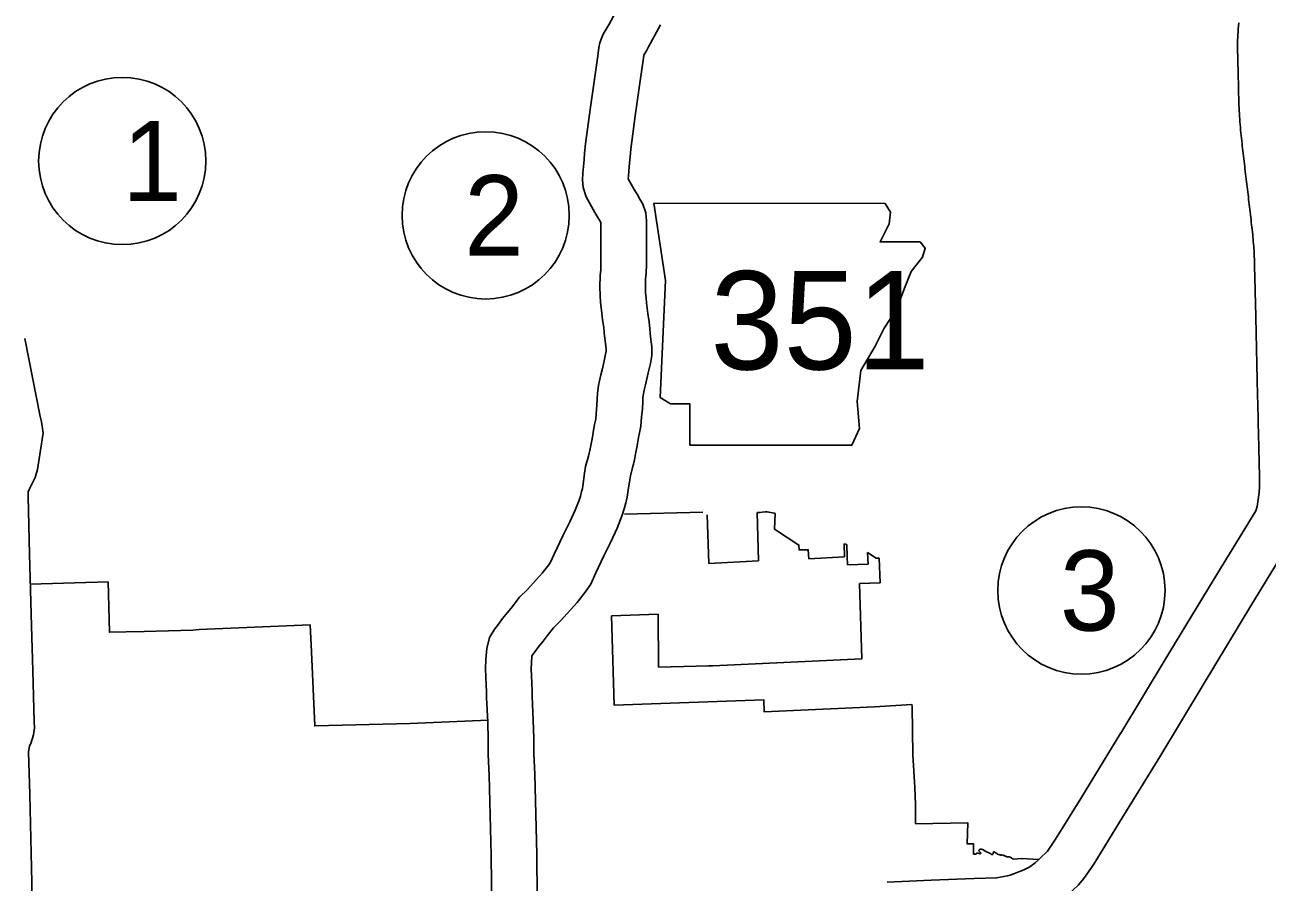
# Model space of a CAD drawing. Extents: x 1671357 to 13005564, y 567358 to 14261451.
# Drawn here: x 12758288.351 to 12758289.241, y 14259954.141 to 14259954.755 of the extents above; entities that cross this region are included whole.
import ezdxf

# ---------------------------------------------------------------- set-up
doc = ezdxf.new("R2010")
doc.units = 0
for name, color, linetype in [('10', 7, 'Continuous'), ('15', 7, 'Continuous'), ('21', 7, 'Continuous'), ('40', 7, 'Continuous'), ('6', 7, 'Continuous')]:
    doc.layers.add(name, color=color, linetype=linetype)

msp = doc.modelspace()

# ---------------------------------------------------------------- linework, layer by layer
at = {"layer": '10'}
for points in [[(12758288.7775, 14259954.76969), (12758288.7693, 14259954.75449), (12758288.7683, 14259954.75271), (12758288.76535, 14259954.74802), (12758288.76398, 14259954.74444), (12758288.76306, 14259954.74171), (12758288.76235, 14259954.73843), (12758288.76145, 14259954.73229), (12758288.7586, 14259954.71236), (12758288.75593, 14259954.69397), (12758288.7526, 14259954.6693), (12758288.75201, 14259954.66267), (12758288.75172, 14259954.6581), (12758288.75124, 14259954.65321), (12758288.75077, 14259954.64835), (12758288.75063, 14259954.64354), (12758288.75105, 14259954.63821), (12758288.75313, 14259954.63138), (12758288.75936, 14259954.62033), (12758288.7615, 14259954.61671), (12758288.76342, 14259954.61343), (12758288.76379, 14259954.6128), (12758288.7637, 14259954.60079), (12758288.76379, 14259954.59004), (12758288.76375, 14259954.58362), (12758288.76365, 14259954.57915), (12758288.76313, 14259954.57511), (12758288.76289, 14259954.5667), (12758288.76312, 14259954.56098), (12758288.76352, 14259954.55592), (12758288.76393, 14259954.55202), (12758288.76435, 14259954.54801), (12758288.76496, 14259954.54325), (12758288.76579, 14259954.53786), (12758288.76619, 14259954.53407), (12758288.76649, 14259954.53009), (12758288.7672, 14259954.52472), (12758288.76758, 14259954.52211), (12758288.76757, 14259954.52091), (12758288.76715, 14259954.51866), (12758288.76582, 14259954.51273), (12758288.76482, 14259954.5085), (12758288.76378, 14259954.504), (12758288.76283, 14259954.49968), (12758288.76213, 14259954.49622), (12758288.7613, 14259954.49083), (12758288.76112, 14259954.48639), (12758288.76084, 14259954.48214), (12758288.76037, 14259954.47635), (12758288.76001, 14259954.47215), (12758288.75918, 14259954.4684), (12758288.75853, 14259954.46427), (12758288.75768, 14259954.45922), (12758288.75642, 14259954.45345), (12758288.75582, 14259954.44987), (12758288.75532, 14259954.44786), (12758288.7548, 14259954.44577), (12758288.7528, 14259954.43841), (12758288.75209, 14259954.43351), (12758288.75098, 14259954.42625), (12758288.75044, 14259954.42264), (12758288.7499, 14259954.42036), (12758288.74902, 14259954.41703), (12758288.74818, 14259954.41431), (12758288.74525, 14259954.40701), (12758288.7414, 14259954.39861), (12758288.73886, 14259954.39355), (12758288.73636, 14259954.38876), (12758288.73036, 14259954.37557), (12758288.72799, 14259954.37033), (12758288.72634, 14259954.36795), (12758288.72164, 14259954.36203), (12758288.71116, 14259954.3503), (12758288.70548, 14259954.34469), (12758288.69935, 14259954.33699), (12758288.69694, 14259954.33375), (12758288.69326, 14259954.32946), (12758288.68961, 14259954.32435), (12758288.6878, 14259954.32201), (12758288.68399, 14259954.31588), (12758288.68195, 14259954.30791), (12758288.68133, 14259954.3001), (12758288.68099, 14259954.29351), (12758288.6816, 14259954.28208), (12758288.68174, 14259954.27693), (12758288.6817, 14259954.27291), (12758288.68263, 14259954.25523), (12758288.683, 14259954.24319), (12758288.68298, 14259954.23201), (12758288.68364, 14259954.21703)], [(12758288.80647, 14259954.75459), (12758288.79794, 14259954.73876), (12758288.7964, 14259954.73602), (12758288.79471, 14259954.73333), (12758288.79461, 14259954.73304), (12758288.79452, 14259954.7326), (12758288.79378, 14259954.72759), (12758288.79093, 14259954.7077), (12758288.78828, 14259954.68944), (12758288.78508, 14259954.66566), (12758288.78459, 14259954.66017), (12758288.78429, 14259954.65545), (12758288.78376, 14259954.65006), (12758288.7834, 14259954.6463), (12758288.78334, 14259954.64434), (12758288.78334, 14259954.64432), (12758288.78334, 14259954.64432), (12758288.78766, 14259954.63667), (12758288.78966, 14259954.63328), (12758288.79167, 14259954.62986), (12758288.7938, 14259954.62615), (12758288.79604, 14259954.62004), (12758288.79647, 14259954.61422), (12758288.79638, 14259954.6008), (12758288.79646, 14259954.59006), (12758288.79641, 14259954.58316), (12758288.79627, 14259954.57672), (12758288.79574, 14259954.57256), (12758288.79558, 14259954.56689), (12758288.79574, 14259954.56291), (12758288.79605, 14259954.55892), (12758288.79642, 14259954.55542), (12758288.7968, 14259954.5518), (12758288.79731, 14259954.54785), (12758288.79821, 14259954.54204), (12758288.79873, 14259954.537), (12758288.799, 14259954.53346), (12758288.79955, 14259954.52925), (12758288.80028, 14259954.52436), (12758288.80021, 14259954.5177), (12758288.79915, 14259954.51206), (12758288.79766, 14259954.5054), (12758288.79664, 14259954.50108), (12758288.79566, 14259954.49682), (12758288.7948, 14259954.49292), (12758288.7943, 14259954.49048), (12758288.79387, 14259954.48766), (12758288.79375, 14259954.48467), (12758288.79343, 14259954.47974), (12758288.79292, 14259954.47363), (12758288.79238, 14259954.46723), (12758288.7913, 14259954.46233), (12758288.79078, 14259954.45901), (12758288.78977, 14259954.45301), (12758288.78851, 14259954.44728), (12758288.78784, 14259954.4432), (12758288.78702, 14259954.43995), (12758288.78643, 14259954.43756), (12758288.78485, 14259954.43176), (12758288.7844, 14259954.42867), (12758288.78328, 14259954.42138), (12758288.78256, 14259954.41645), (12758288.78158, 14259954.41238), (12758288.78043, 14259954.40804), (12758288.77901, 14259954.40341), (12758288.77528, 14259954.39412), (12758288.77087, 14259954.38449), (12758288.76794, 14259954.37865), (12758288.76572, 14259954.37441), (12758288.76012, 14259954.36208), (12758288.75652, 14259954.35413), (12758288.75256, 14259954.34844), (12758288.74663, 14259954.34098), (12758288.73484, 14259954.32777), (12758288.72984, 14259954.32283), (12758288.72523, 14259954.31704), (12758288.72245, 14259954.31331), (12758288.719, 14259954.30929), (12758288.71586, 14259954.3049), (12758288.71469, 14259954.30338), (12758288.71439, 14259954.30289), (12758288.71429, 14259954.30253), (12758288.71394, 14259954.29799), (12758288.71371, 14259954.29355), (12758288.71425, 14259954.2834), (12758288.71442, 14259954.27721), (12758288.71438, 14259954.27359), (12758288.71527, 14259954.2566), (12758288.71567, 14259954.24367), (12758288.71565, 14259954.2327), (12758288.7163, 14259954.21808)], [(12758288.35099, 14259954.53008), (12758288.36195, 14259954.47422), (12758288.36293, 14259954.47025), (12758288.36353, 14259954.46723), (12758288.36418, 14259954.46222), (12758288.3636, 14259954.45769), (12758288.36019, 14259954.43629), (12758288.35846, 14259954.43042), (12758288.35529, 14259954.42427), (12758288.35409, 14259954.42192), (12758288.35338, 14259954.42021), (12758288.3534, 14259954.41673), (12758288.3543, 14259954.37553), (12758288.35577, 14259954.32412), (12758288.35672, 14259954.29219), (12758288.35787, 14259954.25551), (12758288.35795, 14259954.25117), (12758288.35723, 14259954.24606), (12758288.35528, 14259954.24006), (12758288.35452, 14259954.23819), (12758288.3541, 14259954.23667), (12758288.35386, 14259954.23532), (12758288.35376, 14259954.23375), (12758288.35467, 14259954.20361)], [(12758288.68363, 14259954.21731), (12758288.68518, 14259954.1599), (12758288.68575, 14259954.0985), (12758288.68631, 14259954.09041), (12758288.68728, 14259954.08543), (12758288.68876, 14259954.08103), (12758288.69006, 14259954.07809), (12758288.70062, 14259954.052)], [(12758288.71629, 14259954.21818), (12758288.71784, 14259954.1605), (12758288.71841, 14259954.09978), (12758288.71877, 14259954.09468), (12758288.71894, 14259954.09379), (12758288.71924, 14259954.09288), (12758288.72014, 14259954.09085), (12758288.72848, 14259954.07025)], [(12758288.35467, 14259954.20347), (12758288.35603, 14259954.14035), (12758288.357, 14259954.0902), (12758288.35712, 14259954.06486), (12758288.35791, 14259954.02479), (12758288.35812, 14259953.98077)]]:
    msp.add_lwpolyline(points, dxfattribs=at)
at = {"layer": '15'}
for points in [[(12758289.22072, 14259954.75604), (12758289.22048, 14259954.75388), (12758289.22029, 14259954.75172), (12758289.22014, 14259954.74959), (12758289.22002, 14259954.74747), (12758289.21995, 14259954.74567), (12758289.21981, 14259954.74351), (12758289.2198, 14259954.74106), (12758289.21981, 14259954.73909), (12758289.21982, 14259954.73722), (12758289.21981, 14259954.73492), (12758289.21993, 14259954.73279), (12758289.21997, 14259954.73121), (12758289.21999, 14259954.72934), (12758289.22003, 14259954.72725), (12758289.2201, 14259954.72528), (12758289.22015, 14259954.72346), (12758289.22019, 14259954.72154), (12758289.22024, 14259954.71961), (12758289.22029, 14259954.71772), (12758289.22034, 14259954.71586), (12758289.22038, 14259954.714), (12758289.22043, 14259954.71229), (12758289.22044, 14259954.71032), (12758289.22052, 14259954.70831), (12758289.22056, 14259954.70657), (12758289.2206, 14259954.70468), (12758289.22065, 14259954.70277), (12758289.2207, 14259954.70085), (12758289.22076, 14259954.69893), (12758289.22082, 14259954.69697), (12758289.2209, 14259954.69496), (12758289.22099, 14259954.69296), (12758289.2211, 14259954.69098), (12758289.22123, 14259954.68901), (12758289.22136, 14259954.68706), (12758289.2215, 14259954.68514), (12758289.22165, 14259954.68318), (12758289.22181, 14259954.68127)], [(12758289.22181, 14259954.68127), (12758289.222, 14259954.67923), (12758289.22219, 14259954.67725), (12758289.22239, 14259954.67534), (12758289.22259, 14259954.67345), (12758289.2228, 14259954.67157), (12758289.22301, 14259954.6697), (12758289.22322, 14259954.66788), (12758289.22342, 14259954.6661), (12758289.22363, 14259954.66427), (12758289.22384, 14259954.6624), (12758289.22406, 14259954.66053), (12758289.22428, 14259954.65873), (12758289.22448, 14259954.65695), (12758289.2247, 14259954.65511), (12758289.22492, 14259954.65326), (12758289.22514, 14259954.65141), (12758289.22536, 14259954.64959), (12758289.22558, 14259954.64779), (12758289.2258, 14259954.64598), (12758289.22601, 14259954.64413), (12758289.22624, 14259954.64228), (12758289.22646, 14259954.64045), (12758289.22667, 14259954.63867), (12758289.22686, 14259954.63701), (12758289.22706, 14259954.6351), (12758289.22732, 14259954.6331), (12758289.22753, 14259954.63138), (12758289.22775, 14259954.6296), (12758289.22797, 14259954.62776), (12758289.22819, 14259954.62594), (12758289.22841, 14259954.62418), (12758289.22861, 14259954.62237), (12758289.22883, 14259954.6205), (12758289.22905, 14259954.61865), (12758289.22926, 14259954.61689), (12758289.22946, 14259954.61516), (12758289.22966, 14259954.61335), (12758289.22987, 14259954.6115), (12758289.23007, 14259954.6097), (12758289.23027, 14259954.60795), (12758289.23046, 14259954.60624), (12758289.23064, 14259954.60455), (12758289.2308, 14259954.60285), (12758289.23094, 14259954.60136), (12758289.23106, 14259954.59951), (12758289.23126, 14259954.59762), (12758289.23138, 14259954.59618), (12758289.23149, 14259954.5946), (12758289.23159, 14259954.59305), (12758289.23167, 14259954.59166), (12758289.23172, 14259954.59012), (12758289.23179, 14259954.5884), (12758289.23184, 14259954.5868), (12758289.23189, 14259954.58518), (12758289.23193, 14259954.58344), (12758289.23198, 14259954.58179), (12758289.23202, 14259954.58018), (12758289.23206, 14259954.57847), (12758289.2321, 14259954.5768), (12758289.23214, 14259954.57512), (12758289.23218, 14259954.57338), (12758289.23223, 14259954.57168), (12758289.23227, 14259954.57), (12758289.23231, 14259954.56832), (12758289.23235, 14259954.56662), (12758289.2324, 14259954.56492), (12758289.23245, 14259954.56327), (12758289.2325, 14259954.56166), (12758289.23254, 14259954.56002), (12758289.23258, 14259954.55832), (12758289.23262, 14259954.55658), (12758289.23267, 14259954.55485), (12758289.23271, 14259954.55308), (12758289.23275, 14259954.55128), (12758289.2328, 14259954.54951), (12758289.23283, 14259954.54776), (12758289.23287, 14259954.54595), (12758289.2329, 14259954.5441), (12758289.23295, 14259954.54225), (12758289.23299, 14259954.54041), (12758289.23303, 14259954.53856), (12758289.23308, 14259954.53672), (12758289.23312, 14259954.53489), (12758289.23315, 14259954.53306), (12758289.23319, 14259954.53119), (12758289.23323, 14259954.52929), (12758289.23327, 14259954.5274), (12758289.23332, 14259954.52554), (12758289.23336, 14259954.5237), (12758289.2334, 14259954.52186), (12758289.23344, 14259954.51999), (12758289.23348, 14259954.51809), (12758289.23352, 14259954.5162), (12758289.23356, 14259954.51434), (12758289.2336, 14259954.51247), (12758289.23365, 14259954.51058), (12758289.23369, 14259954.50876), (12758289.23372, 14259954.50693), (12758289.23376, 14259954.50508)], [(12758289.23376, 14259954.50508), (12758289.2338, 14259954.50327), (12758289.23383, 14259954.50144), (12758289.23387, 14259954.4996), (12758289.23392, 14259954.49776), (12758289.23397, 14259954.49589), (12758289.23403, 14259954.49405), (12758289.23408, 14259954.49231), (12758289.23412, 14259954.49056), (12758289.23416, 14259954.48876), (12758289.2342, 14259954.48698), (12758289.23425, 14259954.48521), (12758289.2343, 14259954.48347), (12758289.23435, 14259954.48172), (12758289.2344, 14259954.47997), (12758289.23445, 14259954.47829), (12758289.23449, 14259954.47665), (12758289.23453, 14259954.47502), (12758289.23456, 14259954.47334), (12758289.23459, 14259954.47161), (12758289.23462, 14259954.46985), (12758289.23466, 14259954.46811), (12758289.23469, 14259954.4664), (12758289.23473, 14259954.46465), (12758289.23477, 14259954.46287), (12758289.23481, 14259954.4611), (12758289.23486, 14259954.45934), (12758289.23491, 14259954.45757), (12758289.23496, 14259954.45582), (12758289.23501, 14259954.45408), (12758289.23505, 14259954.45235), (12758289.23509, 14259954.45064), (12758289.23512, 14259954.44893), (12758289.23515, 14259954.44721), (12758289.23518, 14259954.44546), (12758289.23522, 14259954.4437), (12758289.23526, 14259954.44196), (12758289.23531, 14259954.44026), (12758289.23535, 14259954.43859), (12758289.23538, 14259954.43692), (12758289.23542, 14259954.43524), (12758289.23545, 14259954.43356), (12758289.23548, 14259954.4319), (12758289.23552, 14259954.43028), (12758289.23555, 14259954.42873), (12758289.23556, 14259954.42747), (12758289.23553, 14259954.42594), (12758289.23555, 14259954.4245), (12758289.23552, 14259954.42359), (12758289.23545, 14259954.42242), (12758289.23536, 14259954.4212), (12758289.23524, 14259954.42007), (12758289.23495, 14259954.41803), (12758289.23396, 14259954.40972), (12758289.23285, 14259954.40661)], [(12758289.23285, 14259954.40661), (12758289.20222, 14259954.35674), (12758289.16721, 14259954.29896), (12758289.13617, 14259954.24734)], [(12758289.26159, 14259954.39098), (12758289.26072, 14259954.38955), (12758289.23011, 14259954.33972), (12758289.19518, 14259954.28208), (12758289.16417, 14259954.2305)], [(12758289.13626, 14259954.24749), (12758289.10743, 14259954.20068), (12758289.08945, 14259954.17149), (12758289.08357, 14259954.16298), (12758289.08225, 14259954.16136), (12758289.07967, 14259954.15906), (12758289.07711, 14259954.15664), (12758289.07473, 14259954.15458), (12758289.07197, 14259954.15246), (12758289.07104, 14259954.15174), (12758289.06727, 14259954.14979), (12758289.06504, 14259954.1488), (12758289.06368, 14259954.14821), (12758289.06007, 14259954.14677), (12758289.057, 14259954.14573), (12758289.05508, 14259954.1451), (12758289.05228, 14259954.14468), (12758289.04723, 14259954.14368), (12758289.03112, 14259954.1432), (12758289.00036, 14259954.14218), (12758288.96889, 14259954.14069)], [(12758289.16408, 14259954.23036), (12758289.13525, 14259954.18355), (12758289.11681, 14259954.15363), (12758289.10972, 14259954.14336), (12758289.10593, 14259954.1387), (12758289.10175, 14259954.13498), (12758289.09904, 14259954.13242), (12758289.09539, 14259954.12925), (12758289.0919, 14259954.12658), (12758289.0887, 14259954.1241), (12758289.08145, 14259954.12034), (12758289.07811, 14259954.11885), (12758289.07615, 14259954.11801), (12758289.0714, 14259954.11612), (12758289.06737, 14259954.11474), (12758289.06262, 14259954.11319), (12758289.05785, 14259954.11248), (12758289.05091, 14259954.11111), (12758289.03216, 14259954.11054), (12758289.00168, 14259954.10953), (12758288.97044, 14259954.10805)]]:
    msp.add_lwpolyline(points, dxfattribs=at)
at = {"layer": '21'}
msp.add_lwpolyline([(12758288.80166, 14259954.62683), (12758288.80995, 14259954.57156), (12758288.80626, 14259954.48773), (12758288.81363, 14259954.48312), (12758288.82745, 14259954.48312), (12758288.82745, 14259954.45364), (12758288.94352, 14259954.45364), (12758288.94905, 14259954.46562), (12758288.94721, 14259954.48496), (12758288.94997, 14259954.50707), (12758288.96011, 14259954.52458), (12758288.96655, 14259954.53747), (12758288.97577, 14259954.55129), (12758288.98129, 14259954.56603), (12758288.9859, 14259954.57801), (12758288.99419, 14259954.58814), (12758288.99603, 14259954.59459), (12758288.99235, 14259954.59919), (12758288.96379, 14259954.59919), (12758288.97024, 14259954.61209), (12758288.97116, 14259954.62038), (12758288.96734, 14259954.62675)], close=True, dxfattribs=at)
at = {"layer": '40'}
for centre in [(12758288.42086, 14259954.65709), (12758288.68122, 14259954.61816), (12758289.10798, 14259954.34954)]:
    msp.add_circle(centre, 0.0599, dxfattribs=at)
at = {"layer": '6'}
for points in [[(12758288.83676, 14259954.40568), (12758288.78073, 14259954.40408)], [(12758288.84095, 14259954.36893), (12758288.83981, 14259954.40377)], [(12758288.87674, 14259954.37068), (12758288.87576, 14259954.40546)], [(12758288.88868, 14259954.40468), (12758288.88797, 14259954.40485), (12758288.88406, 14259954.4057), (12758288.88277, 14259954.40592), (12758288.88149, 14259954.40592), (12758288.8793, 14259954.40561), (12758288.8774, 14259954.40531), (12758288.87595, 14259954.40544)], [(12758288.88848, 14259954.4047), (12758288.88803, 14259954.39356), (12758288.90553, 14259954.38201), (12758288.90567, 14259954.3786), (12758288.91226, 14259954.37867), (12758288.91258, 14259954.3722)], [(12758288.9401, 14259954.37375), (12758288.93983, 14259954.38244), (12758288.93806, 14259954.38285), (12758288.93836, 14259954.37365)], [(12758288.91258, 14259954.3722), (12758288.93836, 14259954.37365)], [(12758288.9401, 14259954.37375), (12758288.94038, 14259954.36789)], [(12758288.94038, 14259954.36789), (12758288.95516, 14259954.36841), (12758288.95477, 14259954.37684)], [(12758288.95477, 14259954.37684), (12758288.96082, 14259954.3728), (12758288.96162, 14259954.3726), (12758288.96313, 14259954.37265)], [(12758288.96313, 14259954.37265), (12758288.96381, 14259954.35504)], [(12758288.84095, 14259954.36893), (12758288.87674, 14259954.37068)], [(12758288.68302, 14259954.25657), (12758288.62713, 14259954.25436), (12758288.5588, 14259954.25252), (12758288.55649, 14259954.30554), (12758288.55554, 14259954.32483), (12758288.47599, 14259954.32159), (12758288.4713, 14259954.32112), (12758288.43645, 14259954.32016), (12758288.42373, 14259954.31993), (12758288.41167, 14259954.31965), (12758288.41065, 14259954.3557), (12758288.35491, 14259954.35401)], [(12758288.96381, 14259954.35504), (12758288.94888, 14259954.35454)], [(12758288.94888, 14259954.35454), (12758288.95071, 14259954.30051)], [(12758288.80465, 14259954.33252), (12758288.77142, 14259954.33137)], [(12758288.95978, 14259954.26632), (12758288.88059, 14259954.26272), (12758288.88037, 14259954.27134), (12758288.77329, 14259954.26739), (12758288.77142, 14259954.33137)], [(12758288.80491, 14259954.29469), (12758288.80465, 14259954.33252)], [(12758288.95071, 14259954.30051), (12758288.84401, 14259954.29563), (12758288.84117, 14259954.29568), (12758288.80491, 14259954.29469)], [(12758288.9868, 14259954.26643), (12758288.98659, 14259954.26787), (12758288.95978, 14259954.26632)], [(12758288.9868, 14259954.26643), (12758288.98723, 14259954.23194)], [(12758288.98723, 14259954.23194), (12758288.98857, 14259954.20835), (12758288.98916, 14259954.19625), (12758288.98916, 14259954.1825), (12758288.98916, 14259954.1824)], [(12758288.98916, 14259954.1825), (12758289.02667, 14259954.18311), (12758289.02621, 14259954.16804), (12758289.03065, 14259954.16822), (12758289.03058, 14259954.16071)], [(12758289.03058, 14259954.16071), (12758289.03126, 14259954.16063), (12758289.03181, 14259954.16062), (12758289.03208, 14259954.16076), (12758289.03245, 14259954.16093), (12758289.03288, 14259954.16119), (12758289.03337, 14259954.16144), (12758289.03367, 14259954.16145), (12758289.03405, 14259954.16132), (12758289.03468, 14259954.16117), (12758289.03493, 14259954.16107), (12758289.03539, 14259954.16105), (12758289.03563, 14259954.16111), (12758289.03574, 14259954.16119), (12758289.03582, 14259954.16125), (12758289.03585, 14259954.16128), (12758289.0359, 14259954.16144), (12758289.03587, 14259954.16163), (12758289.03584, 14259954.16172), (12758289.03564, 14259954.16198), (12758289.03525, 14259954.16228), (12758289.03498, 14259954.16252), (12758289.03472, 14259954.16289), (12758289.03461, 14259954.16306), (12758289.03455, 14259954.16325), (12758289.03452, 14259954.16344), (12758289.03457, 14259954.1636), (12758289.03468, 14259954.16382), (12758289.03486, 14259954.16405), (12758289.035, 14259954.16416), (12758289.03519, 14259954.16422), (12758289.03535, 14259954.16425), (12758289.03573, 14259954.16426), (12758289.03608, 14259954.16426), (12758289.03635, 14259954.16427), (12758289.03671, 14259954.16417), (12758289.03726, 14259954.16399), (12758289.03831, 14259954.16335), (12758289.03957, 14259954.16267), (12758289.04172, 14259954.1616), (12758289.04224, 14259954.16133), (12758289.04274, 14259954.16107), (12758289.04299, 14259954.16089), (12758289.04332, 14259954.16073), (12758289.04359, 14259954.16057), (12758289.04381, 14259954.16049), (12758289.04414, 14259954.16039), (12758289.04433, 14259954.16045), (12758289.04446, 14259954.16062), (12758289.04468, 14259954.16089), (12758289.04473, 14259954.16111), (12758289.0448, 14259954.16166), (12758289.0449, 14259954.16191), (12758289.04495, 14259954.16216), (12758289.04532, 14259954.16233), (12758289.04546, 14259954.16236), (12758289.04579, 14259954.1622), (12758289.04623, 14259954.16194), (12758289.04665, 14259954.16165), (12758289.0469, 14259954.16146), (12758289.04734, 14259954.16114), (12758289.04778, 14259954.16082), (12758289.04803, 14259954.16069), (12758289.04841, 14259954.16056), (12758289.04893, 14259954.16044), (12758289.04929, 14259954.16034), (12758289.04984, 14259954.16019), (12758289.0503, 14259954.16009), (12758289.05065, 14259954.16012), (12758289.0509, 14259954.16026), (12758289.05188, 14259954.16007), (12758289.05232, 14259954.15986), (12758289.05284, 14259954.15959), (12758289.0535, 14259954.15928), (12758289.05397, 14259954.15913), (12758289.05419, 14259954.15902), (12758289.05493, 14259954.15868), (12758289.05556, 14259954.15872), (12758289.05621, 14259954.15871), (12758289.05654, 14259954.15866), (12758289.05698, 14259954.15859), (12758289.05736, 14259954.15838), (12758289.0578, 14259954.1582), (12758289.05819, 14259954.1579), (12758289.05869, 14259954.15745), (12758289.05905, 14259954.15729), (12758289.05924, 14259954.15724), (12758289.06511, 14259954.15753), (12758289.07729, 14259954.15682)]]:
    msp.add_lwpolyline(points, dxfattribs=at)

# ---------------------------------------------------------------- texts
at = {"layer": '21'}
msp.add_text('351', height=0.07044, dxfattribs=at).set_placement((12758288.84221, 14259954.50781))
at = {"layer": '40'}
for s, p in [('1', (12758288.42086, 14259954.62834)), ('2', (12758288.66579, 14259954.58941)), ('3', (12758289.09254, 14259954.32079))]:
    msp.add_text(s, height=0.0575, dxfattribs=at).set_placement(p)

doc.saveas('drawing.dxf')
